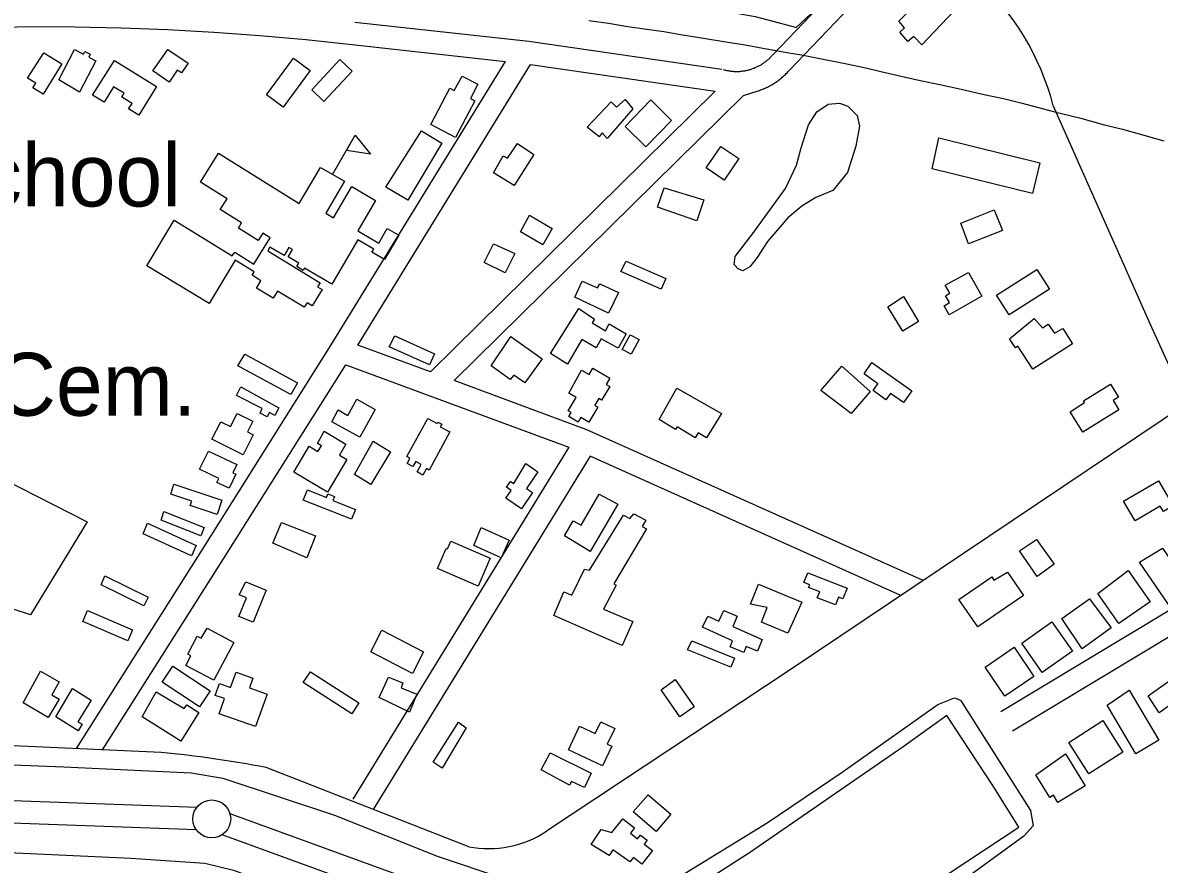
# Model space of a CAD drawing. Extents: x 3540316 to 3578335, y 553172 to 578787.
# Drawn here: x 3548021 to 3549520, y 568472 to 569583 of the extents above; entities that cross this region are included whole.
import ezdxf

# ---------------------------------------------------------------- set-up
doc = ezdxf.new("R2010")
doc.units = 0
for name, color, linetype in [('V-BLDG-IDEN', 7, 'Continuous'), ('V-BLDG-OTLN', 7, 'Continuous'), ('V-LEVE-TOET', 7, 'Continuous'), ('V-RAIL-TRAK', 7, 'Continuous'), ('V-ROAD-CNTR', 7, 'Continuous'), ('V-SITE-OTLN', 7, 'Continuous'), ('V-SITE-OTLN-IDEN', 7, 'Continuous'), ('V-SITE-VEGE', 7, 'Continuous'), ('V-SURV-LINE', 7, 'Continuous'), ('V-TOPO-SHOR', 7, 'Continuous')]:
    doc.layers.add(name, color=color, linetype=linetype)

msp = doc.modelspace()

# ---------------------------------------------------------------- linework, layer by layer
at = {"layer": 'V-BLDG-OTLN'}
msp.add_line((3548429.4, 569382.1), (3548459.2, 569434.2), dxfattribs=at)
for points in [[(3549188.1, 569557.9), (3549177.9, 569569.9), (3549183.8, 569575.8), (3549176.4, 569584.7), (3549187.5, 569595.5), (3549158.8, 569621.6), (3549172.4, 569635.5), (3549177.6, 569632.4), (3549199.5, 569655.8), (3549218.6, 569637.1), (3549202.2, 569619.8), (3549207.8, 569615.8), (3549229.3, 569635.2), (3549258.3, 569607.5), (3549206.6, 569553.3), (3549196.4, 569564.4)], [(3548048.7, 569542.8), (3548072.4, 569528.4), (3548047.8, 569488.1), (3548034.2, 569496.5), (3548038, 569502.7), (3548027, 569509.4)], [(3548089.3, 569547.1), (3548101, 569541), (3548102.9, 569544.6), (3548110, 569541), (3548107.9, 569537.1), (3548117.4, 569532.1), (3548095.7, 569490.9), (3548068.4, 569507.4)], [(3548212.2, 569547.2), (3548239, 569529), (3548230.3, 569516.3), (3548224.7, 569520.1), (3548214, 569504.2), (3548192.5, 569519.1)], [(3548112.7, 569487.1), (3548141.7, 569532.8), (3548197.5, 569498.2), (3548174, 569460.4), (3548160.5, 569468.8), (3548165, 569476), (3548151.5, 569484.3), (3548154.6, 569489.4), (3548140.8, 569498), (3548128.1, 569477.6)], [(3548342.5, 569487.6), (3548378.2, 569536), (3548399.8, 569519.7), (3548364.4, 569471.3)], [(3548402, 569493.8), (3548439, 569534), (3548455.5, 569518.5), (3548418, 569478.7)], [(3548600.6, 569512.2), (3548621.3, 569501.4), (3548611.4, 569482.6), (3548617, 569479.7), (3548591.7, 569431.2), (3548559.1, 569448.3), (3548584.3, 569496.4), (3548590.1, 569493.3)], [(3548765.4, 569444.8), (3548796.8, 569478), (3548803.9, 569471.3), (3548815.6, 569481.1), (3548825.5, 569469), (3548791.9, 569430), (3548785.1, 569437.1), (3548781.1, 569431.8)], [(3548815.5, 569445.5), (3548849.3, 569480.9), (3548876.8, 569453.4), (3548842.6, 569418.7)], [(3548546.8, 569439.8), (3548573.5, 569423.8), (3548528.6, 569348.5), (3548500, 569365.5)], [(3548459.2, 569434.2), (3548479.5, 569409.3), (3548447.7, 569414.1)], [(3548654.4, 569406.9), (3548660.2, 569403.8), (3548673.5, 569423.2), (3548695, 569408.7), (3548669.2, 569367.8), (3548641.8, 569384.7)], [(3549229.3, 569430.8), (3549362.6, 569397.8), (3549352.6, 569357.2), (3549220.2, 569389.9)], [(3548220.7, 569322.1), (3548297.3, 569274.9), (3548300.5, 569280), (3548325.7, 569264.2), (3548347.1, 569298.6), (3548337.4, 569304.7), (3548331.5, 569295.2), (3548305.3, 569311.5), (3548309.6, 569318.5), (3548281.4, 569336.1), (3548290.3, 569350.2), (3548255.3, 569372.1), (3548279.3, 569410.4), (3548385.7, 569344), (3548413.8, 569391.7), (3548445.1, 569373.7), (3548420.5, 569331.1), (3548430.8, 569325.1), (3548454.8, 569366.5), (3548486.3, 569348.2), (3548462.8, 569307.8), (3548490.5, 569291.7), (3548501.7, 569311), (3548516.8, 569302.2), (3548497.9, 569270), (3548481.5, 569279.6), (3548483.9, 569283.8), (3548462.8, 569296.1), (3548428.7, 569237.8), (3548392.7, 569258.8), (3548390.9, 569255.7), (3548382.4, 569260.7), (3548385.1, 569265.4), (3548371.1, 569273.5), (3548376.8, 569283.2), (3548371.8, 569286.1), (3548365.7, 569275.6), (3548347, 569286.5), (3548344.1, 569281.6), (3548413, 569239.2), (3548409.8, 569233.9), (3548415.6, 569230.4), (3548402.7, 569209), (3548395.9, 569213.1), (3548392.2, 569207.1), (3548356.9, 569228.3), (3548351.4, 569219.1), (3548329.2, 569232.4), (3548335, 569242.2), (3548323.3, 569249.3), (3548326.1, 569254), (3548301, 569269.1), (3548266.9, 569212.3), (3548184.4, 569261.8)], [(3548941.7, 569419.4), (3548965.4, 569403.4), (3548946.1, 569374.9), (3548922.1, 569391.1)], [(3548866.9, 569364.8), (3548919.2, 569348.7), (3548910, 569321.1), (3548858, 569339.3)], [(3549258.3, 569318.3), (3549302.3, 569335.8), (3549313.2, 569308.5), (3549268.3, 569290.6)], [(3548689.2, 569328.7), (3548719.4, 569311.1), (3548706.9, 569289.7), (3548677.3, 569306.6)], [(3548669.9, 569278.2), (3548657.3, 569252.5), (3548629.6, 569266.1), (3548641.8, 569290.9)], [(3548816.7, 569267.9), (3548869, 569245.1), (3548862.9, 569231.1), (3548809.8, 569254.2)], [(3549305.1, 569223.2), (3549358.4, 569257), (3549375, 569230.8), (3549321.8, 569197)], [(3548758.8, 569241.5), (3548779, 569232.8), (3548782, 569238.2), (3548806.6, 569226.7), (3548793.7, 569199.4), (3548748.9, 569220.5)], [(3549268.2, 569253), (3549286, 569221.9), (3549242.9, 569197.1), (3549236.1, 569209.1), (3549243.2, 569213.2), (3549238, 569222.3), (3549243.8, 569225.6), (3549237.7, 569236.2)], [(3549182.5, 569221.2), (3549202.5, 569188.3), (3549181.6, 569175.5), (3549161.9, 569207.9)], [(3548775, 569191.2), (3548771.9, 569186.6), (3548789.7, 569176.1), (3548794.4, 569185.4), (3548816.8, 569172.1), (3548806.4, 569153), (3548783.9, 569165.4), (3548777.1, 569153.7), (3548758.3, 569164.7), (3548739.2, 569132.1), (3548717.1, 569146.3), (3548754.3, 569205.7)], [(3549355.1, 569192.4), (3549365.9, 569179.8), (3549373.3, 569184.7), (3549381.9, 569173), (3549392.7, 569179.2), (3549405.6, 569158.9), (3549353, 569125.3), (3549333.6, 569155.8), (3549330.1, 569153.5), (3549322.4, 569165.5)], [(3548511.8, 569169.4), (3548564.2, 569145.8), (3548557.5, 569131), (3548504.4, 569154.9)], [(3548664.7, 569168.7), (3548706, 569139.2), (3548683.2, 569107.2), (3548668.6, 569117.6), (3548663.7, 569111.8), (3548638.8, 569129.9)], [(3548833.8, 569164.8), (3548823.3, 569145.1), (3548811.6, 569151.4), (3548822, 569170.9)], [(3548313.6, 569145.3), (3548383.2, 569107.4), (3548374.7, 569091.8), (3548304.8, 569129.9)], [(3548758, 569124.3), (3548767.8, 569118.4), (3548772.8, 569126.8), (3548795.4, 569113.4), (3548790.6, 569105.2), (3548795.2, 569102.5), (3548784.4, 569084.4), (3548780.8, 569086.6), (3548775.6, 569077.9), (3548779.5, 569075.5), (3548767.5, 569055.3), (3548757, 569061.6), (3548753.5, 569055.7), (3548741.1, 569063.1), (3548744.1, 569068.2), (3548740.3, 569070.4), (3548750.7, 569088), (3548741.2, 569093.6)], [(3549073.6, 569097.2), (3549101.3, 569129.5), (3549138.4, 569096), (3549113.4, 569067)], [(3549141, 569134.1), (3549193.4, 569096.9), (3549182.4, 569081.5), (3549165.5, 569093.5), (3549159.4, 569085), (3549142.4, 569097.1), (3549148.9, 569106.3), (3549130.5, 569119.4)], [(3548358.7, 569074.6), (3548353.4, 569064.4), (3548346.2, 569068.1), (3548343.4, 569062.6), (3548333.9, 569067.5), (3548336.9, 569073.4), (3548303, 569090.9), (3548308.4, 569102.2)], [(3548860.1, 569059.2), (3548883.8, 569100.5), (3548942.4, 569067.1), (3548922.8, 569034.7), (3548911.9, 569041.5), (3548907.7, 569034.7), (3548884.2, 569049.3), (3548882, 569045.7)], [(3549402.4, 569069.2), (3549421.4, 569081.6), (3549420.1, 569083.6), (3549455.4, 569105.8), (3549466.2, 569088.5), (3549459, 569084), (3549466.7, 569071.7), (3549419.3, 569042.1)], [(3548428.7, 569056.1), (3548437, 569071.6), (3548449.8, 569064.5), (3548461.5, 569085.7), (3548485.6, 569072.4), (3548465.4, 569035.8)], [(3548282.2, 569056.1), (3548295.1, 569049.7), (3548303.8, 569067), (3548324.4, 569056.7), (3548317.4, 569042.8), (3548325, 569039), (3548311.7, 569012.4), (3548270.2, 569033.1)], [(3548527.6, 569010), (3548555, 569060.5), (3548567.3, 569053.8), (3548568.4, 569055.6), (3548573.5, 569052.9), (3548571.6, 569049.5), (3548584.2, 569042.6), (3548556.9, 568992.3), (3548553.5, 568994.2), (3548548.8, 568985.6), (3548541.1, 568989.8), (3548546.5, 568999.8), (3548539.2, 569003.7), (3548535.4, 568996.8), (3548527.9, 569000.9), (3548531.6, 569007.7)], [(3548418.6, 569043.5), (3548447.2, 569026.6), (3548438.6, 569012.1), (3548448.5, 569006.3), (3548423, 568963.1), (3548378.3, 568989.5), (3548398.5, 569023.8), (3548410.3, 569016.8), (3548414.8, 569024.5), (3548409.8, 569027.4)], [(3548265.7, 569017.3), (3548303.3, 568999.7), (3548298.1, 568988.6), (3548301.9, 568986.8), (3548293.3, 568968.5), (3548277.1, 568976), (3548279.6, 568981.3), (3548253.9, 568993.3)], [(3548483.2, 569030.3), (3548506, 569016.4), (3548479.9, 568973.4), (3548458.5, 568986.4)], [(3548684.6, 569001), (3548700.4, 568990.1), (3548685.3, 568968.2), (3548693.3, 568962.7), (3548678.6, 568941.3), (3548658, 568955.4), (3548665, 568965.4), (3548659, 568969.6), (3548664.3, 568977.3), (3548668.7, 568974.5)], [(3548216.1, 568960.3), (3548220.3, 568973.6), (3548283.5, 568952.5), (3548277.2, 568933.6), (3548241.9, 568945.4), (3548243.8, 568951.1)], [(3549472.8, 568951.1), (3549518.8, 568978.1), (3549538.4, 568945.2), (3549525.5, 568937.5), (3549521.1, 568944.8), (3549488.2, 568925.2)], [(3548396.5, 568966.1), (3548421.7, 568956.2), (3548423.5, 568960.9), (3548432, 568957.6), (3548429.8, 568952), (3548459.6, 568940.4), (3548454.6, 568927.4), (3548390.6, 568952.4)], [(3548781.3, 568960.3), (3548805.9, 568947.3), (3548769.4, 568884.7), (3548735.3, 568905.4), (3548746.8, 568925.4), (3548757.5, 568919.6)], [(3548207.2, 568937.5), (3548260.2, 568916.6), (3548255.9, 568905.7), (3548203.5, 568926.4)], [(3548843.6, 568914.6), (3548800.5, 568842.3), (3548803.5, 568840.5), (3548786.8, 568808.7), (3548825.8, 568792.7), (3548811.6, 568760.7), (3548721.4, 568800.4), (3548734.6, 568831.5), (3548745.1, 568827.2), (3548761.7, 568861.7), (3548768.5, 568860.1), (3548813.1, 568932.8), (3548821.7, 568928.2), (3548826.7, 568934.6), (3548842.7, 568926.3), (3548838.1, 568918)], [(3548185.3, 568922.1), (3548249.7, 568892.6), (3548243.5, 568879.1), (3548179.7, 568908.3)], [(3548362.1, 568923.1), (3548407, 568905.6), (3548395.7, 568876.5), (3548350.7, 568895.7)], [(3548625.5, 568916.5), (3548662.3, 568900), (3548651.8, 568876.6), (3548615.9, 568892.7)], [(3548585.6, 568898.6), (3548637.6, 568876.1), (3548621.7, 568839.3), (3548568.1, 568862.4), (3548579.5, 568888.9), (3548581.3, 568888.2)], [(3549358, 568900.6), (3549381.4, 568868.2), (3549358.9, 568851.9), (3549335.8, 568885.8)], [(3549524.3, 568889.4), (3549561.5, 568834.9), (3549532.2, 568814.9), (3549493.9, 568870.9)], [(3548129.1, 568852.8), (3548186.1, 568824.4), (3548180.4, 568813.1), (3548124.2, 568841.1)], [(3549056.6, 568856.7), (3549108.1, 568836.7), (3549102.5, 568822.4), (3549096.7, 568824.7), (3549092.7, 568814.4), (3549068.9, 568823.6), (3549072.1, 568831.8), (3549057.5, 568837.5), (3549058.9, 568841), (3549051.2, 568844)], [(3549319.7, 568857.6), (3549340.9, 568826.8), (3549280.6, 568785.3), (3549255.6, 568821.5), (3549298.9, 568851.4), (3549301.9, 568847.1)], [(3549479, 568859.8), (3549507.8, 568818.4), (3549466.5, 568789.7), (3549439, 568829.3)], [(3548315.2, 568844.7), (3548342, 568833.7), (3548324.6, 568791.6), (3548305.8, 568799.3), (3548316, 568823.9), (3548306.5, 568827.8)], [(3548980.6, 568815.4), (3548991.4, 568841.6), (3549048.5, 568818.1), (3549030.2, 568777.2), (3548995.1, 568791.7), (3549002.8, 568810.8)], [(3549391.4, 568796.5), (3549427.9, 568822.2), (3549456.3, 568784.2), (3549418.3, 568756.5)], [(3548106.3, 568807.2), (3548165.7, 568781.3), (3548159.4, 568766.8), (3548100.1, 568792.6)], [(3548996, 568768.9), (3548989.8, 568753.5), (3548975, 568759.4), (3548972, 568751.8), (3548953.8, 568759.1), (3548957.1, 568767.2), (3548917.5, 568784.9), (3548924.3, 568799.4), (3548939, 568792.9), (3548945.5, 568807.1), (3548963.4, 568799.4), (3548957.5, 568785.8)], [(3549378.3, 568791.9), (3549405.4, 568753.4), (3549365.6, 568725.4), (3549338.5, 568763.8)], [(3548264.1, 568783.8), (3548299.5, 568765), (3548273, 568714.9), (3548236, 568734.5), (3548242.8, 568747.3), (3548238.5, 568749.6), (3548251, 568773.2), (3548256.3, 568770.3)], [(3548494.5, 568781), (3548549.6, 568752.3), (3548534.9, 568724), (3548480, 568752.5)], [(3548903.3, 568767), (3548959.7, 568744.3), (3548954.8, 568732.2), (3548897.7, 568755.2)], [(3549328.4, 568758.6), (3549354.6, 568719.8), (3549316.1, 568693.8), (3549290.3, 568732.1)], [(3548204.7, 568712.4), (3548218.9, 568733.6), (3548268.3, 568701.1), (3548254.2, 568679.8)], [(3548044.1, 568727.1), (3548069.1, 568712.9), (3548059.3, 568695.8), (3548068.8, 568690.2), (3548054.5, 568665.7), (3548021.3, 568685)], [(3548302.6, 568725.6), (3548324.5, 568717.9), (3548319.9, 568704.8), (3548343.1, 568696.6), (3548328.1, 568653.8), (3548279.8, 568670.8), (3548286.8, 568690.7), (3548274.9, 568694.9), (3548280.5, 568710.7), (3548295.1, 568705.5)], [(3548400.4, 568726), (3548464.2, 568685), (3548454.9, 568670.5), (3548390.7, 568711.8)], [(3548503.3, 568719.2), (3548522.4, 568711.5), (3548519.8, 568704.9), (3548540.5, 568696.5), (3548530.9, 568672.8), (3548491, 568692.1)], [(3549505.5, 568694.3), (3549543.3, 568721.1), (3549571.4, 568682), (3549550.4, 568666.6), (3549538.4, 568685.1), (3549519.9, 568672.1)], [(3548086.3, 568704.3), (3548111.2, 568688.9), (3548093.6, 568660.3), (3548099.2, 568656.9), (3548094, 568648.4), (3548064.6, 568666.5)], [(3548881.5, 568716), (3548906.5, 568680), (3548887.4, 568666.7), (3548862.8, 568702.2)], [(3549451, 568682.3), (3549480.4, 568702), (3549519.3, 568635.9), (3549488.9, 568617.9)], [(3548196.8, 568699.7), (3548233.8, 568677.6), (3548237.1, 568682.7), (3548253.3, 568672.3), (3548229.2, 568634.6), (3548178.6, 568666.9)], [(3548595.7, 568659.7), (3548605.7, 568652.3), (3548574, 568599.2), (3548562.4, 568607)], [(3548755.2, 568654.5), (3548775.9, 568644.7), (3548783.3, 568660.2), (3548801.7, 568651.4), (3548791.9, 568630.8), (3548798, 568627.9), (3548785.7, 568601.9), (3548740.9, 568623.1)], [(3549400.5, 568633), (3549445.5, 568661.7), (3549471.9, 568620.1), (3549427, 568591.4)], [(3548770.7, 568592.3), (3548762, 568573.5), (3548744.5, 568581.6), (3548742, 568576.5), (3548704.5, 568596.6), (3548716.5, 568619.1)], [(3549396.2, 568617.9), (3549422.1, 568575.7), (3549386.3, 568553.8), (3549380.6, 568563.2), (3549375.6, 568560.1), (3549357.1, 568590.2)], [(3548845.9, 568563.7), (3548875.8, 568538.4), (3548856.4, 568515.4), (3548826, 568541.2)], [(3548812.2, 568532.1), (3548827.9, 568520.4), (3548822.5, 568513.1), (3548831.9, 568505.8), (3548835.7, 568510.7), (3548844.4, 568503.9), (3548840.6, 568498.9), (3548851.4, 568490.5), (3548837.6, 568472.4), (3548826.6, 568480.9), (3548821.6, 568475.4), (3548799, 568491.1), (3548794.4, 568483.7), (3548770.6, 568498.2), (3548783.9, 568518.2), (3548797.7, 568513.9)]]:
    msp.add_lwpolyline(points, close=True, dxfattribs=at)
at = {"layer": 'V-LEVE-TOET'}
for points in [[(3547740.4, 568609.2), (3547885.3, 568608.2), (3548075.1, 568600.8), (3548243, 568593), (3548285, 568586), (3548432, 568537), (3548569, 568482.3), (3548652.6, 568454.3), (3548695, 568434.6), (3548805.3, 568365.5), (3548919, 568290.6), (3549032.2, 568209.9), (3549190.9, 568099.3), (3549381.1, 567967.7), (3549524, 567870.8), (3549685.8, 567762.2), (3549864, 567644.5), (3550011.8, 567540.4), (3550143.1, 567453.9), (3550243.6, 567377.8)], [(3547729.2, 568503.5), (3547828.5, 568500.7), (3547982.8, 568488.8), (3548163.5, 568480.2), (3548261.1, 568473.6), (3548299, 568464.6), (3548431.9, 568415.2), (3548585.9, 568358), (3548641.4, 568332.1), (3548774, 568244.8), (3548846.9, 568197.5), (3549000.4, 568092.2), (3549141.2, 568002.9), (3549282.4, 567907.4), (3549428.5, 567807), (3549582.3, 567707.3), (3549721.7, 567617.3), (3549855.6, 567525.7), (3550026.9, 567407.2), (3550093.6, 567363.1)]]:
    msp.add_lwpolyline(points, dxfattribs=at)
at = {"layer": 'V-RAIL-TRAK'}
msp.add_lwpolyline([(3548767.4, 569585.7), (3548793.7, 569581.9), (3548819, 569577.6), (3548844.2, 569574.2), (3548866.6, 569570.9), (3548888.3, 569567), (3548916.2, 569562.5), (3548948.4, 569557.3), (3548973.6, 569553.3), (3548997, 569549.2), (3549031.2, 569542.9), (3549048.1, 569540), (3549076.8, 569534.6), (3549105.7, 569528.7), (3549133.1, 569522.9), (3549152.8, 569518.1), (3549175.5, 569513), (3549204.5, 569506.4), (3549230.7, 569501), (3549262.4, 569493.9), (3549287, 569488.3), (3549314.6, 569482.4), (3549337.5, 569476.8), (3549360.7, 569470.7), (3549383.3, 569464.5), (3549414.7, 569457), (3549446, 569448.4), (3549471.5, 569441.9), (3549496.6, 569434.9), (3549525.9, 569426.8)], dxfattribs=at)
at = {"layer": 'V-ROAD-CNTR'}
for points in [[(3549182, 569720.1), (3549010.3, 569540.4)], [(3549203.7, 569699.3), (3549032, 569519.7)], [(3547998.3, 569576.9), (3548028.5, 569577.4), (3548089.8, 569577), (3548150.7, 569575.9), (3548211.7, 569573.7), (3548272.9, 569570.1), (3548333.8, 569565.8), (3548394.4, 569560.4), (3548455.4, 569553.7)], [(3548458.7, 569583.5), (3548688.5, 569558.2), (3548943, 569521.1)], [(3548455.4, 569553.7), (3548657.6, 569531.4)], [(3548091.7, 568624.8), (3548260.3, 568891.2), (3548427.9, 569157.4), (3548657.6, 569531.4)], [(3548463, 569157.2), (3548690.4, 569527.6)], [(3548690.4, 569527.6), (3548934.3, 569492.1)], [(3548944.9, 569520.7), (3548945.9, 569520.5), (3548946.9, 569520.2), (3548948, 569519.9), (3548949, 569519.7), (3548950.2, 569519.5), (3548951.3, 569519.3), (3548952.3, 569519.1), (3548953.4, 569518.9), (3548954.5, 569518.8), (3548955.6, 569518.6), (3548956.7, 569518.5), (3548957.8, 569518.5), (3548958.9, 569518.4), (3548960, 569518.3), (3548961.1, 569518.3), (3548962.2, 569518.3), (3548963.3, 569518.3), (3548964.4, 569518.3), (3548965.5, 569518.4), (3548966.6, 569518.4), (3548967.7, 569518.5), (3548968.8, 569518.6), (3548969.9, 569518.8), (3548971, 569518.9), (3548972.1, 569519.1), (3548973.2, 569519.2), (3548974.2, 569519.4), (3548975.3, 569519.6), (3548976.4, 569519.9), (3548977.4, 569520.1), (3548978.5, 569520.4), (3548979.6, 569520.7), (3548980.6, 569521), (3548981.7, 569521.3), (3548982.7, 569521.7), (3548983.8, 569522.1), (3548984.8, 569522.4), (3548985.8, 569522.8), (3548986.8, 569523.3), (3548987.9, 569523.7), (3548988.9, 569524.2), (3548989.8, 569524.6), (3548990.9, 569525.1), (3548991.8, 569525.6), (3548992.8, 569526.1), (3548993.8, 569526.7), (3548994.7, 569527.2), (3548995.6, 569527.8), (3548996.6, 569528.4), (3548997.5, 569529), (3548998.4, 569529.6), (3548999.3, 569530.3), (3549000.2, 569530.9), (3549001, 569531.6), (3549001.9, 569532.3), (3549002.8, 569533), (3549003.6, 569533.7), (3549004.4, 569534.4), (3549005.2, 569535.1), (3549006.1, 569535.9), (3549006.8, 569536.7), (3549007.6, 569537.5), (3549008.4, 569538.3), (3549009.1, 569539.1), (3549009.9, 569540)], [(3548971.4, 569486.6), (3548990.9, 569492.8), (3548992.5, 569493.3), (3548993.9, 569493.8), (3548995.5, 569494.4), (3548997, 569495), (3548998.5, 569495.6), (3549000, 569496.3), (3549001.5, 569496.9), (3549003, 569497.6), (3549004.4, 569498.3), (3549005.9, 569499.1), (3549007.3, 569499.9), (3549008.7, 569500.7), (3549010.1, 569501.5), (3549011.5, 569502.3), (3549012.9, 569503.2), (3549014.2, 569504.1), (3549015.5, 569505), (3549016.9, 569506), (3549018.2, 569506.9), (3549019.5, 569507.9), (3549020.7, 569508.9), (3549022, 569509.9), (3549023.2, 569511), (3549024.5, 569512.1), (3549025.7, 569513.2), (3549026.8, 569514.3), (3549028, 569515.4), (3549029.2, 569516.6), (3549030.2, 569517.7), (3549031.4, 569519), (3549032.4, 569520.1)], [(3548934.3, 569492.1), (3548558.8, 569121.8)], [(3548971.4, 569486.6), (3548589.9, 569110.3)], [(3549380.1, 569473), (3549507.6, 569185.7), (3549752, 568647.6)], [(3548558.8, 569121.8), (3548463, 569157.2)], [(3548126.2, 568623.2), (3548285.7, 568875.2), (3548446.9, 569131.2)], [(3548446.9, 569131.2), (3548741.1, 569022.4)], [(3549208.4, 568846.6), (3548765.1, 569045.5), (3548589.9, 569110.3)], [(3549555.9, 569079.5), (3549032.9, 568728.9), (3548711.7, 568515.8)], [(3548741.1, 569022.4), (3548456.3, 568558)], [(3548769.2, 569010.8), (3548483.2, 568544.6)], [(3549179, 568826.9), (3548769.2, 569010.8)], [(3549311, 568673.9), (3549646.5, 568875.7)], [(3549326.5, 568648.2), (3549662, 568850)], [(3548203.3, 568619.8), (3547285.4, 568660.8), (3545892.6, 568705.2)], [(3548609.2, 568495.4), (3548341.8, 568599.9)]]:
    msp.add_lwpolyline(points, dxfattribs=at)
for centre, radius, start, end in [((3549048.5, 569387), 342.6, 14.5283, 47.8544), ((3548046.4, 567034.9), 1592.6, 79.3109, 84.3462), ((3548635.7, 568629.5), 136.7, 258.804, 303.7608)]:
    msp.add_arc(centre, radius, start, end, dxfattribs=at)
at = {"layer": 'V-SITE-OTLN'}
msp.add_lwpolyline([(3547761, 568661.1), (3547802.5, 568734.8), (3547891, 568869), (3547972.5, 568991.6), (3548105.9, 568924.2), (3548031, 568801.5), (3547964.7, 568822.9), (3547863.9, 568647.5)], close=True, dxfattribs=at)
at = {"layer": 'V-SITE-VEGE'}
msp.add_lwpolyline([(3548964.5, 569258), (3548959.4, 569263.5), (3548960.7, 569274.2), (3548983.9, 569304.6), (3549027, 569363.9), (3549041.5, 569394.6), (3549047.7, 569417.3), (3549057.4, 569448), (3549068.4, 569465.2), (3549083.3, 569475.2), (3549098.1, 569476.5), (3549109.2, 569472.6), (3549121.4, 569460), (3549124.4, 569446.1), (3549119.8, 569419.5), (3549108.8, 569384.9), (3549089.4, 569361), (3549067.1, 569351.9), (3549048.3, 569340.6), (3549030.2, 569325), (3549003, 569294), (3548989.5, 569272.9), (3548979.7, 569260.6), (3548970.7, 569255.1)], close=True, dxfattribs=at)
for points in [[(3548875.3, 568448.5), (3549002.8, 568526.8), (3549101.8, 568593.5), (3549228, 568682.8), (3549250, 568691.9), (3549257.8, 568688.6), (3549350.3, 568543), (3549353.6, 568523), (3549341.3, 568509.4), (3549195.7, 568403.2)], [(3549131.6, 568387), (3549334.8, 568521), (3549300.5, 568576), (3549239.6, 568668.6), (3549182, 568627.1), (3548979.5, 568487.3), (3548842.3, 568399.3)]]:
    msp.add_lwpolyline(points, dxfattribs=at)
at = {"layer": 'V-SURV-LINE'}
for points in [[(3545755.6, 568637.9), (3548250.8, 568547.7)], [(3548249.7, 568517.8), (3545754.5, 568607.9)], [(3548294.1, 568539.3), (3548654.9, 568407.6)], [(3548644.6, 568379.4), (3548283.8, 568511.1)]]:
    msp.add_lwpolyline(points, dxfattribs=at)
msp.add_circle((3548270.2, 568532), 25, dxfattribs=at)
at = {"layer": 'V-TOPO-SHOR'}
msp.add_line((3549072.6, 569605.9), (3549041, 569576.1), dxfattribs=at)
msp.add_lwpolyline([(3548422.3, 569910.2), (3548481.6, 569859), (3548542.6, 569804.2), (3548617.3, 569736.3), (3548664.8, 569695.1), (3548703.8, 569659.8), (3548724, 569643), (3548737.6, 569636.5), (3548767, 569628.5), (3548842.4, 569613.3), (3548927.6, 569601.5), (3548986.8, 569590.7), (3549033.6, 569578.3), (3549041, 569576.1)], dxfattribs=at)

# ---------------------------------------------------------------- texts
at = {"layer": 'V-BLDG-IDEN'}
msp.add_text('School', height=83, dxfattribs=at).set_placement((3547890.2, 569340.1))
at = {"layer": 'V-SITE-OTLN-IDEN'}
msp.add_text('Cem.', height=83, dxfattribs=at).set_placement((3547984.5, 569064))

doc.saveas('drawing.dxf')
